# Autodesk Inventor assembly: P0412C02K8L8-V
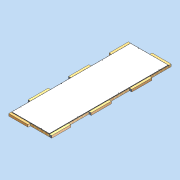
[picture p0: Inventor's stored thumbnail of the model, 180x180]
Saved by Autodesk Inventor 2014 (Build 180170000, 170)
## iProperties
Created: 2011-04
Part Number: P0412C02K8L8-V
Document SubType Name: Assembly
Designer: david.appleford
Description: 1w x 3w 02 Ceiling Panel - 8 Locks 8 Lugs
Mass: 78000 g
Surface Area: 104094 cm^2
Volume: 363866 cm^3
Density: 0.214365 g/cm^3
Cost Center: £248.00
Justset: False
Author: david.appleford
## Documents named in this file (4)
- C:\Documents and Settings\john.everitt\Local Settings\My Documents\Vault\Production MkII\VIRTUAL ELEMENTS\Virtual Ceilings\Ceiling MgO & Timber Frame\P0412C02K8L8-V.iam
- C:\Documents and Settings\john.everitt\Local Settings\My Documents\Vault\Production MkII\VIRTUAL ELEMENTS\Virtual Lugs\Superceded Lugs\LA02C3V.ipt
- C:\Documents and Settings\john.everitt\Local Settings\My Documents\Vault\Production MkII\VIRTUAL ELEMENTS\Virtual Lugs\Superceded Lugs\LA02M3V.ipt
- C:\Documents and Settings\john.everitt\Local Settings\My Documents\Vault\Production MkII\VIRTUAL ELEMENTS\Virtual Ceilings\Ceiling MgO & Timber Frame\P0412C02K8-V.ipt
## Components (9 placed, 3 different names)
1. P0412C02K8-V:1 — Mate:1, Flush:1, Flush:2, Mate:2, Flush:3, Flush:4, Mate:3, Flush:5, Flush:6, Mate:4, Flush:7, Flush:8, Mate:5, Mate:6, Flush:9, Flush:10, Mate:7, Mate:8, Flush:11, Flush:12
2. LA02C3V:1 — Mate:1, Flush:1, Flush:2, Mate:9
3. LA02C3V:2 — Mate:2, Flush:3, Flush:4
4. LA02C3V:3 — Mate:4, Flush:7, Flush:8
5. LA02C3V:4 — Mate:3, Flush:5, Flush:6, Mate:11
6. LA02M3V:1 — Mate:6, Flush:9, Mate:11, Mate:12
7. LA02M3V:2 — Mate:5, Flush:10, Mate:12
8. LA02M3V:3 — Mate:8, Flush:12, Mate:10
9. LA02M3V:4 — Mate:7, Flush:11, Mate:9, Mate:10
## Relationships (24: Mate 12, Flush 12)
- Mate:1: P0412C02K8-V:1 ↔ LA02C3V:1
- Flush:1: P0412C02K8-V:1 ↔ LA02C3V:1
- Flush:2: P0412C02K8-V:1 ↔ LA02C3V:1
- Mate:2: P0412C02K8-V:1 ↔ LA02C3V:2
- Flush:3: P0412C02K8-V:1 ↔ LA02C3V:2
- Flush:4: P0412C02K8-V:1 ↔ LA02C3V:2
- Mate:3: P0412C02K8-V:1 ↔ LA02C3V:4
- Flush:5: P0412C02K8-V:1 ↔ LA02C3V:4
- Flush:6: P0412C02K8-V:1 ↔ LA02C3V:4
- Mate:4: P0412C02K8-V:1 ↔ LA02C3V:3
- Flush:7: P0412C02K8-V:1 ↔ LA02C3V:3
- Flush:8: P0412C02K8-V:1 ↔ LA02C3V:3
- Mate:5: P0412C02K8-V:1 ↔ LA02M3V:2
- Mate:6: P0412C02K8-V:1 ↔ LA02M3V:1
- Flush:9: P0412C02K8-V:1 ↔ LA02M3V:1
- Flush:10: P0412C02K8-V:1 ↔ LA02M3V:2
- Mate:7: P0412C02K8-V:1 ↔ LA02M3V:4
- Mate:8: P0412C02K8-V:1 ↔ LA02M3V:3
- Flush:11: P0412C02K8-V:1 ↔ LA02M3V:4
- Flush:12: P0412C02K8-V:1 ↔ LA02M3V:3
- Mate:9: LA02C3V:1 ↔ LA02M3V:4
- Mate:10: LA02M3V:3 ↔ LA02M3V:4
- Mate:11: LA02C3V:4 ↔ LA02M3V:1
- Mate:12: LA02M3V:1 ↔ LA02M3V:2
## Named parameters: t = 1 mm, Cl = 2 mm
